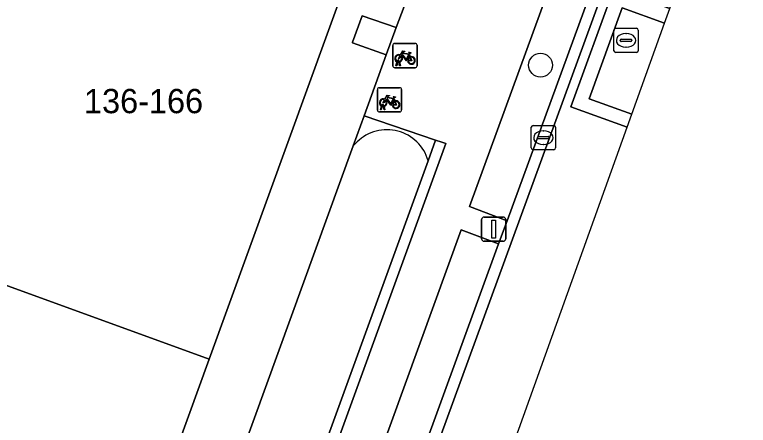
# Model space of a CAD drawing. Extents: x 155887 to 156869, y 383880 to 384678.
# Drawn here: x 156669.01 to 156699.23, y 383933.64 to 383950.56 of the extents above; entities that cross this region are included whole.
import ezdxf

# ---------------------------------------------------------------- set-up
doc = ezdxf.new("R2010")
doc.units = 0
for name, color, linetype in [('IMGEO_Boom', 7, 'Continuous'), ('IMGEO_Fietsenrek', 7, 'Continuous'), ('IMGEO_Greppel_droge_sloot', 7, 'Continuous'), ('IMGEO_Groenvoorziening', 7, 'Continuous'), ('IMGEO_Haag', 7, 'Continuous'), ('IMGEO_Kolk', 7, 'Continuous'), ('IMGEO_Lichtmast', 7, 'Continuous'), ('IMGEO_Pand', 7, 'Continuous'), ('IMGEO_Pand_nummerreeks', 7, 'Continuous'), ('IMGEO_Parkeervlak_open', 7, 'Continuous'), ('IMGEO_Rijbaan_lokaal_open', 7, 'Continuous'), ('IMGEO_Rioolput', 7, 'Continuous'), ('IMGEO_Verkeerseiland_groen', 7, 'Continuous'), ('IMGEO_Voetpad_op_trap', 7, 'Continuous'), ('IMGEO_Voetpad_open', 7, 'Continuous')]:
    doc.layers.add(name, color=color, linetype=linetype)

msp = doc.modelspace()

# ---------------------------------------------------------------- linework, layer by layer
at = {"layer": 'IMGEO_Boom'}
msp.add_circle((156690.673, 383948.48), 0.489, dxfattribs=at)
at = {"layer": 'IMGEO_Fietsenrek'}
for p, q in [((156684.585, 383948.45), (156684.585, 383949.291)), ((156684.585, 383949.291), (156684.585, 383948.45)), ((156684.66, 383949.375), (156685.501, 383949.375)), ((156685.501, 383949.375), (156684.66, 383949.375)), ((156685.585, 383949.3), (156685.585, 383948.459)), ((156685.585, 383948.459), (156685.585, 383949.3)), ((156685.272, 383948.924), (156685.308, 383948.829)), ((156684.712, 383948.459), (156684.751, 383948.619)), ((156684.781, 383948.607), (156684.746, 383948.459)), ((156684.823, 383948.631), (156684.822, 383948.635)), ((156684.864, 383948.459), (156684.83, 383948.601)), ((156684.854, 383948.642), (156684.855, 383948.635)), ((156684.862, 383948.605), (156684.897, 383948.459)), ((156685.51, 383948.375), (156684.669, 383948.375)), ((156684.669, 383948.375), (156685.51, 383948.375)), ((156684.746, 383948.459), (156684.712, 383948.459)), ((156684.897, 383948.459), (156684.864, 383948.459)), ((156683.951, 383946.628), (156683.951, 383947.469)), ((156683.951, 383947.469), (156683.951, 383946.628)), ((156684.026, 383947.553), (156684.867, 383947.553)), ((156684.867, 383947.553), (156684.026, 383947.553)), ((156684.951, 383947.478), (156684.951, 383946.637)), ((156684.951, 383946.637), (156684.951, 383947.478)), ((156684.638, 383947.102), (156684.674, 383947.007)), ((156684.078, 383946.637), (156684.117, 383946.797)), ((156684.147, 383946.785), (156684.112, 383946.637)), ((156684.189, 383946.809), (156684.188, 383946.813)), ((156684.23, 383946.637), (156684.196, 383946.779)), ((156684.22, 383946.82), (156684.221, 383946.813)), ((156684.228, 383946.783), (156684.263, 383946.637)), ((156684.876, 383946.553), (156684.035, 383946.553)), ((156684.035, 383946.553), (156684.876, 383946.553)), ((156684.112, 383946.637), (156684.078, 383946.637)), ((156684.263, 383946.637), (156684.23, 383946.637))]:
    msp.add_line(p, q, dxfattribs=at)
for points in [[(156684.919, 383948.849), (156684.867, 383948.759), (156684.827, 383948.734), (156684.828, 383948.781), (156684.883, 383948.875)], [(156684.898, 383948.901), (156684.993, 383949.065), (156685.079, 383949.051), (156685.081, 383949.042), (156685.025, 383949.031), (156684.998, 383948.986), (156685.254, 383948.945)], [(156685.194, 383948.657), (156685.144, 383948.657), (156684.953, 383948.908), (156684.934, 383948.876)], [(156685.241, 383948.92), (156684.984, 383948.961), (156684.967, 383948.932), (156685.134, 383948.712), (156685.241, 383948.92)], [(156685.289, 383948.822), (156685.259, 383948.899), (156685.15, 383948.681), (156685.193, 383948.681)], [(156685.254, 383948.945), (156685.279, 383948.994), (156685.273, 383948.998), (156685.25, 383949.002), (156685.238, 383949.009), (156685.237, 383949.012), (156685.239, 383949.017), (156685.334, 383949.002), (156685.336, 383948.992), (156685.326, 383948.979), (156685.314, 383948.973), (156685.3, 383948.979), (156685.272, 383948.924)], [(156685.223, 383948.681), (156685.343, 383948.68), (156685.299, 383948.794)], [(156685.319, 383948.801), (156685.374, 383948.656), (156685.224, 383948.656)], [(156684.285, 383947.027), (156684.233, 383946.937), (156684.193, 383946.912), (156684.194, 383946.959), (156684.249, 383947.053)], [(156684.264, 383947.079), (156684.359, 383947.243), (156684.445, 383947.229), (156684.447, 383947.22), (156684.391, 383947.209), (156684.364, 383947.164), (156684.62, 383947.123)], [(156684.56, 383946.835), (156684.51, 383946.835), (156684.319, 383947.086), (156684.3, 383947.054)], [(156684.607, 383947.098), (156684.35, 383947.139), (156684.333, 383947.11), (156684.5, 383946.89), (156684.607, 383947.098)], [(156684.655, 383947), (156684.625, 383947.077), (156684.516, 383946.859), (156684.559, 383946.859)], [(156684.62, 383947.123), (156684.645, 383947.172), (156684.639, 383947.176), (156684.616, 383947.18), (156684.604, 383947.187), (156684.603, 383947.19), (156684.605, 383947.195), (156684.7, 383947.18), (156684.702, 383947.17), (156684.692, 383947.157), (156684.68, 383947.151), (156684.666, 383947.157), (156684.638, 383947.102)], [(156684.589, 383946.859), (156684.709, 383946.858), (156684.665, 383946.972)], [(156684.685, 383946.979), (156684.74, 383946.834), (156684.59, 383946.834)]]:
    msp.add_lwpolyline(points, dxfattribs=at)
for centre, radius, start, end in [((156684.663, 383949.297), 0.0779, 92.4484, 184.2845), ((156684.663, 383949.297), 0.0779, 92.4484, 184.2845), ((156685.507, 383949.297), 0.0779, 2.4484, 94.2845), ((156685.507, 383949.297), 0.0779, 2.4484, 94.2845), ((156684.825, 383948.76), 0.159, 62.6766, 242.1369), ((156684.825, 383948.76), 0.129, 63.3192, 238.903), ((156684.825, 383948.76), 0.129, 283.6043, 43.4302), ((156684.825, 383948.76), 0.159, 283.5766, 46.6042), ((156684.805, 383948.631), 0.0499, 12.8025, 158.6934), ((156684.825, 383948.76), 0.159, 253.9967, 271.7867), ((156684.805, 383948.631), 0.0174, 12.8025, 163.4502), ((156684.825, 383948.76), 0.129, 253.415, 269.0204), ((156685.352, 383948.676), 0.159, 113.3408, 178.3217), ((156685.352, 383948.676), 0.159, 187.0065, 105.7708), ((156685.352, 383948.676), 0.129, 113.923, 177.9556), ((156685.352, 383948.676), 0.129, 188.6715, 104.5883), ((156684.663, 383948.453), 0.0779, 182.4484, 274.2845), ((156684.663, 383948.453), 0.0779, 182.4484, 274.2845), ((156685.507, 383948.453), 0.0779, 272.4484, 4.2845), ((156685.507, 383948.453), 0.0779, 272.4484, 4.2845), ((156684.029, 383947.475), 0.0779, 92.4484, 184.2845), ((156684.029, 383947.475), 0.0779, 92.4484, 184.2845), ((156684.873, 383947.475), 0.0779, 2.4484, 94.2845), ((156684.873, 383947.475), 0.0779, 2.4484, 94.2845), ((156684.191, 383946.938), 0.159, 62.6766, 242.1369), ((156684.191, 383946.938), 0.129, 63.3192, 238.903), ((156684.191, 383946.938), 0.159, 283.5766, 46.6042), ((156684.171, 383946.809), 0.0499, 12.8025, 158.6934), ((156684.191, 383946.938), 0.159, 253.9967, 271.7867), ((156684.171, 383946.809), 0.0174, 12.8025, 163.4502), ((156684.191, 383946.938), 0.129, 253.415, 269.0204), ((156684.191, 383946.938), 0.129, 283.6043, 43.4302), ((156684.718, 383946.854), 0.159, 113.3408, 178.3217), ((156684.718, 383946.854), 0.159, 187.0065, 105.7708), ((156684.718, 383946.854), 0.129, 113.923, 177.9556), ((156684.718, 383946.854), 0.129, 188.6715, 104.5883), ((156684.029, 383946.631), 0.0779, 182.4484, 274.2845), ((156684.029, 383946.631), 0.0779, 182.4484, 274.2845), ((156684.873, 383946.631), 0.0779, 272.4484, 4.2845), ((156684.873, 383946.631), 0.0779, 272.4484, 4.2845)]:
    msp.add_arc(centre, radius, start, end, dxfattribs=at)
at = {"layer": 'IMGEO_Greppel_droge_sloot'}
for points in [[(156683.114, 383945.318), (156682.955, 383945.153), (156673.753, 383919.791), (156673.566, 383919.215)], [(156676.107, 383917.245), (156686.039, 383944.544)]]:
    msp.add_lwpolyline(points, dxfattribs=at)
msp.add_arc((156684.347, 383944.063), 1.759, 15.8773, 134.4795, dxfattribs=at)
at = {"layer": 'IMGEO_Groenvoorziening'}
msp.add_lwpolyline([(156686.348, 383945.394), (156686.039, 383944.544), (156676.107, 383917.245), (156675.892, 383916.653), (156676.136, 383916.563), (156676.314, 383916.497), (156686.775, 383945.25), (156686.611, 383945.305)], close=True, dxfattribs=at)
at = {"layer": 'IMGEO_Haag'}
msp.add_lwpolyline([(156686.611, 383945.305), (156686.348, 383945.394), (156686.039, 383944.544), (156676.107, 383917.245), (156675.892, 383916.653), (156676.136, 383916.563), (156676.314, 383916.497), (156686.775, 383945.25)], close=True, dxfattribs=at)
at = {"layer": 'IMGEO_Kolk'}
for p, q in [((156690.291, 383945.068), (156690.291, 383945.92)), ((156690.366, 383945.994), (156691.218, 383945.994)), ((156691.292, 383945.92), (156691.292, 383945.068)), ((156690.593, 383945.537), (156690.991, 383945.537)), ((156690.779, 383945.774), (156690.804, 383945.774)), ((156690.55, 383945.488), (156690.55, 383945.5)), ((156690.988, 383945.451), (156690.59, 383945.451)), ((156691.034, 383945.5), (156691.034, 383945.488)), ((156691.218, 383944.994), (156690.366, 383944.994)), ((156690.802, 383945.214), (156690.777, 383945.214))]:
    msp.add_line(p, q, dxfattribs=at)
for points in [[(156690.291, 383945.068), (156690.291, 383945.92)], [(156690.366, 383945.994), (156691.218, 383945.994)], [(156691.292, 383945.92), (156691.292, 383945.068)], [(156691.218, 383944.994), (156690.366, 383944.994)]]:
    msp.add_lwpolyline(points, dxfattribs=at)
for centre, radius, start, end in [((156690.368, 383945.918), 0.0765, 91.552, 178.448), ((156690.368, 383945.918), 0.0765, 91.552, 178.448), ((156691.216, 383945.918), 0.0765, 1.552, 88.448), ((156691.216, 383945.918), 0.0765, 1.552, 88.448), ((156690.59, 383945.497), 0.0403, 85.8775, 175.7526), ((156690.995, 383945.499), 0.0386, 1.7309, 96.639), ((156690.587, 383945.487), 0.0366, 178.938, 274.7102), ((156690.991, 383945.494), 0.043, 264.8664, 352.4533), ((156690.368, 383945.07), 0.0765, 181.552, 268.448), ((156690.368, 383945.07), 0.0765, 181.552, 268.448), ((156691.216, 383945.07), 0.0765, 271.552, 358.448), ((156691.216, 383945.07), 0.0765, 271.552, 358.448)]:
    msp.add_arc(centre, radius, start, end, dxfattribs=at)
for centre, major_axis, ratio, start_param, end_param in [((156690.778, 383945.494), (-0.387, 0.002), 0.722429, 4.712389, 7.853982), ((156690.803, 383945.494), (-0.39, 0.002), 0.717154, 1.570796, 4.712389)]:
    msp.add_ellipse(centre, major_axis=major_axis, ratio=ratio, start_param=start_param, end_param=end_param, dxfattribs=at)
at = {"layer": 'IMGEO_Lichtmast'}
for p, q in [((156688.347, 383942.223), (156689.137, 383942.223)), ((156689.137, 383942.223), (156688.347, 383942.223)), ((156688.247, 383941.323), (156688.247, 383942.123)), ((156688.247, 383942.123), (156688.247, 383941.323)), ((156689.237, 383942.123), (156689.237, 383941.323)), ((156689.237, 383941.323), (156689.237, 383942.123)), ((156689.137, 383941.223), (156688.347, 383941.223)), ((156688.347, 383941.223), (156689.137, 383941.223))]:
    msp.add_line(p, q, dxfattribs=at)
msp.add_lwpolyline([(156688.667, 383942.098), (156688.817, 383942.098), (156688.817, 383941.348), (156688.667, 383941.348), (156688.667, 383942.098)], dxfattribs=at)
for centre, start, end in [((156688.347, 383942.123), 90, 180), ((156688.347, 383942.123), 90, 180), ((156689.137, 383942.123), 0, 90), ((156689.137, 383942.123), 360, 90), ((156688.347, 383941.323), 180, 270), ((156688.347, 383941.323), 180, 270), ((156689.137, 383941.323), 270, 0), ((156689.137, 383941.323), 270, 0)]:
    msp.add_arc(centre, 0.1, start, end, dxfattribs=at)
at = {"layer": 'IMGEO_Pand'}
for points in [[(156683.556, 383954.382), (156671.051, 383958.927), (156664.506, 383940.92), (156677.017, 383936.373)], [(156661.304, 383932.108), (156651.646, 383923.717), (156664.695, 383908.697), (156666.298, 383906.852), (156666.729, 383908.038), (156677.017, 383936.373), (156664.506, 383940.92)]]:
    msp.add_lwpolyline(points, close=True, dxfattribs=at)
at = {"layer": 'IMGEO_Parkeervlak_open'}
for points in [[(156689.296, 383942.063), (156696.603, 383962.067), (156695.036, 383962.635), (156687.747, 383942.663)], [(156688.947, 383941.115), (156687.397, 383941.697), (156681.102, 383924.33), (156682.626, 383923.772)]]:
    msp.add_lwpolyline(points, close=True, dxfattribs=at)
at = {"layer": 'IMGEO_Rijbaan_lokaal_open'}
for points in [[(156677.675, 383899.767), (156694.244, 383945.927), (156691.926, 383946.766), (156693.691, 383951.644), (156695.997, 383950.81), (156716.432, 384007.739), (156714.276, 384008.493), (156715.998, 384013.414), (156718.193, 384012.646), (156728.468, 384041.271)], [(156725.263, 384039.726), (156724.872, 384039.789), (156724.434, 384038.612), (156717.913, 384020.742), (156717.572, 384019.8), (156710.389, 384000), (156710.062, 383999.099), (156709.703, 383998.205), (156707.835, 383992.994), (156705.569, 383986.715), (156703.687, 383981.463), (156703.318, 383980.473), (156700.912, 383973.902), (156696.603, 383962.067), (156689.296, 383942.063), (156688.947, 383941.115), (156682.626, 383923.772), (156682.257, 383922.839), (156680.383, 383917.674), (156676.156, 383906.083)], [(156676.593, 383905.923), (156697.031, 383961.901), (156710.148, 383998.003), (156710.873, 384000), (156724.824, 384038.423), (156725.263, 384039.726)], [(156725.263, 384039.726), (156724.824, 384038.423), (156710.873, 384000), (156710.148, 383998.003), (156697.031, 383961.901), (156676.593, 383905.923)]]:
    msp.add_lwpolyline(points, dxfattribs=at)
for points in [[(156694.244, 383945.927), (156694.437, 383946.464), (156692.68, 383947.097), (156694.038, 383950.848), (156695.782, 383950.211), (156695.997, 383950.81), (156693.691, 383951.644), (156691.926, 383946.766)], [(156694.437, 383946.464), (156695.782, 383950.211), (156694.038, 383950.848), (156692.68, 383947.097)]]:
    msp.add_lwpolyline(points, close=True, dxfattribs=at)
at = {"layer": 'IMGEO_Rioolput'}
for p, q in [((156693.697, 383949.076), (156693.697, 383949.928)), ((156693.772, 383950.002), (156694.624, 383950.002)), ((156694.185, 383949.782), (156694.21, 383949.782)), ((156694.698, 383949.928), (156694.698, 383949.076)), ((156693.956, 383949.496), (156693.956, 383949.508)), ((156694.394, 383949.459), (156693.996, 383949.459)), ((156693.999, 383949.545), (156694.397, 383949.545)), ((156694.44, 383949.508), (156694.44, 383949.496)), ((156694.208, 383949.222), (156694.183, 383949.222)), ((156694.624, 383949.002), (156693.772, 383949.002))]:
    msp.add_line(p, q, dxfattribs=at)
for points in [[(156693.697, 383949.076), (156693.697, 383949.928)], [(156693.772, 383950.002), (156694.624, 383950.002)], [(156694.698, 383949.928), (156694.698, 383949.076)], [(156694.624, 383949.002), (156693.772, 383949.002)]]:
    msp.add_lwpolyline(points, dxfattribs=at)
for centre, radius, start, end in [((156693.774, 383949.926), 0.0765, 91.552, 178.448), ((156693.774, 383949.926), 0.0765, 91.552, 178.448), ((156694.622, 383949.926), 0.0765, 1.552, 88.448), ((156694.622, 383949.926), 0.0765, 1.552, 88.448), ((156693.996, 383949.505), 0.0403, 85.8775, 175.7526), ((156693.993, 383949.495), 0.0366, 178.938, 274.7102), ((156694.397, 383949.502), 0.043, 264.8664, 352.4533), ((156694.401, 383949.507), 0.0386, 1.7309, 96.639), ((156693.774, 383949.078), 0.0765, 181.552, 268.448), ((156693.774, 383949.078), 0.0765, 181.552, 268.448), ((156694.622, 383949.078), 0.0765, 271.552, 358.448), ((156694.622, 383949.078), 0.0765, 271.552, 358.448)]:
    msp.add_arc(centre, radius, start, end, dxfattribs=at)
for centre, major_axis, ratio, start_param, end_param in [((156694.184, 383949.502), (-0.387, 0.002), 0.722429, 4.712389, 7.853982), ((156694.209, 383949.502), (-0.39, 0.002), 0.717154, 1.570796, 4.712389)]:
    msp.add_ellipse(centre, major_axis=major_axis, ratio=ratio, start_param=start_param, end_param=end_param, dxfattribs=at)
at = {"layer": 'IMGEO_Verkeerseiland_groen'}
msp.add_lwpolyline([(156686.039, 383944.544), (156686.348, 383945.394), (156683.403, 383946.387), (156682.955, 383945.153), (156683.114, 383945.318)], dxfattribs=at)
msp.add_arc((156684.347, 383944.063), 1.759, 15.8773, 134.4795, dxfattribs=at)
at = {"layer": 'IMGEO_Voetpad_op_trap'}
msp.add_lwpolyline([(156684.724, 383950.028), (156683.324, 383950.506), (156682.931, 383949.427), (156682.921, 383949.398), (156684.316, 383948.904)], close=True, dxfattribs=at)
at = {"layer": 'IMGEO_Voetpad_open'}
for points in [[(156696.42, 383989.808), (156689.95, 383971.991), (156683.556, 383954.382), (156677.017, 383936.373), (156666.729, 383908.038)], [(156669.502, 383908.349), (156673, 383917.716), (156673.753, 383919.791), (156682.955, 383945.153), (156683.403, 383946.387), (156684.316, 383948.904), (156682.921, 383949.398), (156682.931, 383949.427), (156683.324, 383950.506), (156684.724, 383950.028), (156685.277, 383951.483), (156685.397, 383951.814), (156686.572, 383955.053), (156695.292, 383979.081), (156695.822, 383980.541), (156696.625, 383982.753), (156695.219, 383983.268), (156695.62, 383984.373), (156697.031, 383983.874), (156697.553, 383985.338), (156697.796, 383986.008), (156698.943, 383989.169)], [(156680.383, 383917.674), (156678.888, 383918.213), (156680.765, 383923.378), (156682.257, 383922.839), (156682.626, 383923.772), (156681.102, 383924.33), (156687.397, 383941.697), (156688.947, 383941.115), (156689.296, 383942.063), (156687.747, 383942.663), (156695.036, 383962.635), (156696.603, 383962.067), (156700.912, 383973.902)], [(156685.277, 383951.483), (156684.724, 383950.028), (156684.316, 383948.904), (156683.403, 383946.387), (156686.348, 383945.394), (156686.611, 383945.305), (156686.775, 383945.25), (156676.314, 383916.497), (156676.136, 383916.563), (156675.892, 383916.653), (156673, 383917.716), (156669.502, 383908.349)]]:
    msp.add_lwpolyline(points, dxfattribs=at)

# ---------------------------------------------------------------- texts
at = {"layer": 'IMGEO_Pand_nummerreeks'}
msp.add_text('136-166', height=1, dxfattribs=at).set_placement((156671.862, 383946.501))

doc.saveas('drawing.dxf')
